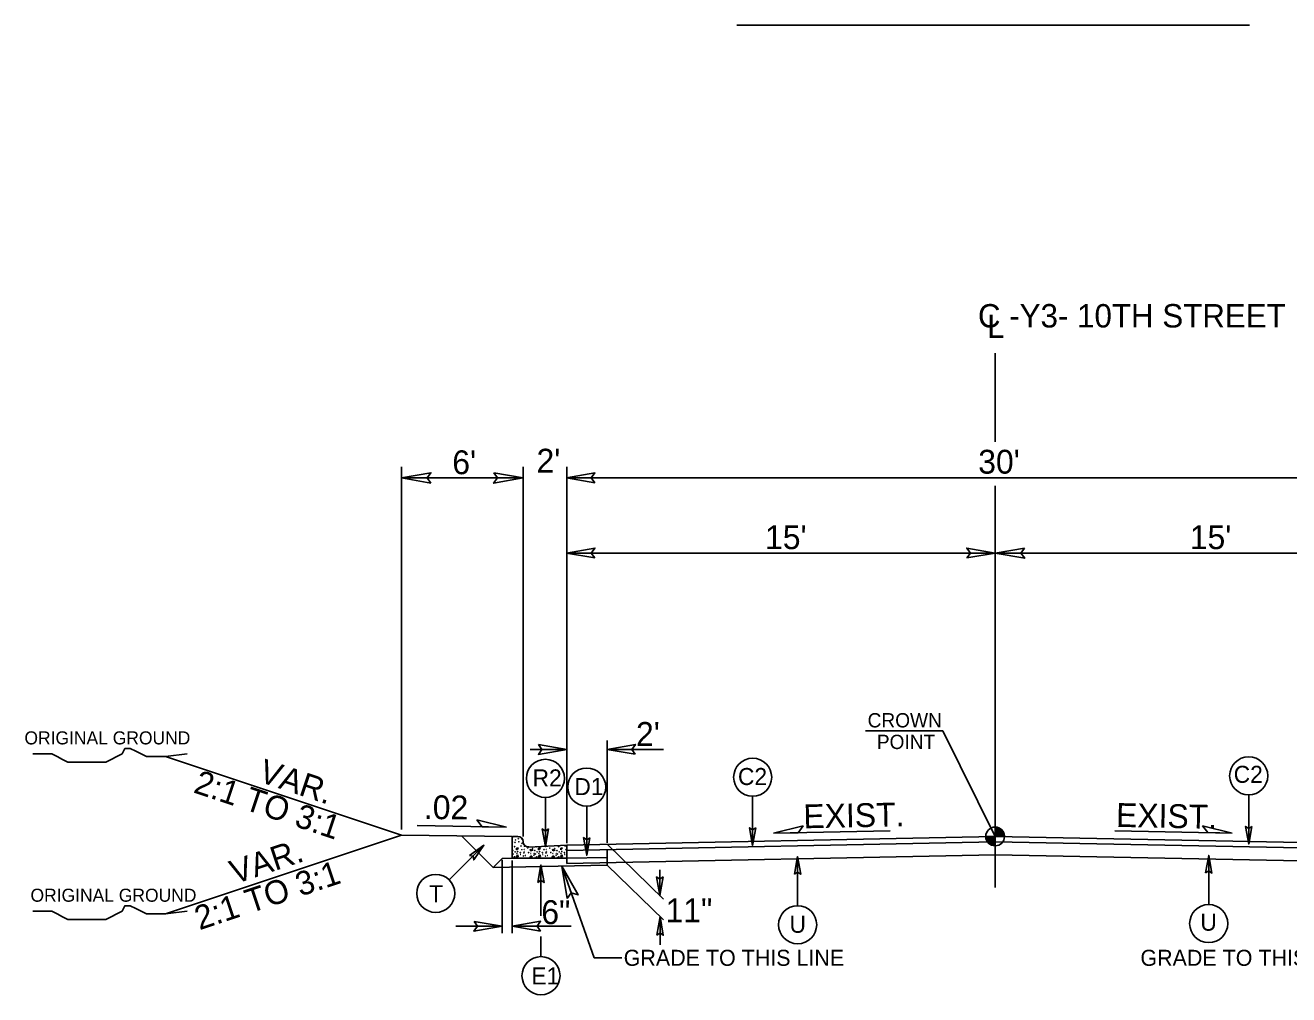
# Model space of a CAD drawing. Extents: x 957297 to 961629, y 830661 to 840840.
# Drawn here: x 959120.4 to 959533.8, y 835054.8 to 835371.9 of the extents above; entities that cross this region are included whole.
import ezdxf

# ---------------------------------------------------------------- set-up
doc = ezdxf.new("R2010")
doc.units = 0
for name, color, linetype in [('Default', 7, 'Continuous'), ('Old_Level_1', 7, 'Continuous'), ('Old_Level_11', 7, 'Continuous'), ('Old_Level_21', 7, 'Continuous'), ('Old_Level_3', 7, 'Continuous'), ('Prop Dimension Text', 7, 'Continuous'), ('Typical ID Circle CELL', 7, 'Continuous'), ('Typical Terminator CELL', 7, 'Continuous'), ('Typical Text Grade Point CELL', 7, 'Continuous'), ('Typical Text ID Circle CELL', 7, 'Continuous')]:
    doc.layers.add(name, color=color, linetype=linetype)

msp = doc.modelspace()

# ---------------------------------------------------------------- linework, layer by layer
at = {"layer": 'Default'}
for p, q in [((959437.72, 835264.61), (959437.72, 835235.64)), ((959437.72, 835221.25), (959437.72, 835089.87))]:
    msp.add_line(p, q, dxfattribs=at)
at = {"layer": 'Old_Level_1'}
for p, q in [((959520.94, 835371.89), (959353.24, 835371.89)), ((959243.49, 835108.77), (959243.49, 835227.43)), ((959283.31, 835106.54), (959283.31, 835227.43)), ((959297.55, 835104.3), (959297.55, 835227.43)), ((959243.49, 835223.8), (959283.31, 835223.8)), ((959297.55, 835223.8), (959577.94, 835223.8)), ((959297.5, 835199.24), (959437.72, 835199.24)), ((959437.72, 835199.24), (959577.94, 835199.24)), ((959285.62, 835135), (959297.55, 835135)), ((959310.76, 835104.5), (959310.76, 835137.93)), ((959310.76, 835135), (959329.24, 835135)), ((959243.49, 835106.92), (959166.3, 835132.65)), ((959248.67, 835110.14), (959277.89, 835109.56)), ((959437.72, 835106.53), (959437.72, 835109.6)), ((959166.3, 835081.19), (959243.49, 835106.92)), ((959243.49, 835106.92), (959279.75, 835106.56)), ((959273.48, 835096.4), (959263.16, 835106.72)), ((959437.72, 835106.54), (959297.55, 835103.71)), ((959403.38, 835108.39), (959365.21, 835107.62)), ((959434.66, 835106.53), (959437.72, 835106.53)), ((959437.72, 835106.54), (959577.94, 835103.71)), ((959440.78, 835106.53), (959437.72, 835106.53)), ((959437.72, 835103.49), (959437.72, 835106.53)), ((959437.72, 835106.53), (959437.72, 835103.49)), ((959476.83, 835108.43), (959515.29, 835107.66)), ((959437.72, 835104.82), (959297.55, 835101.98)), ((959437.72, 835104.82), (959297.55, 835101.98)), ((959297.55, 835101.98), (959297.55, 835097.71)), ((959310.76, 835103.98), (959329.23, 835086.05)), ((959310.76, 835102.25), (959310.76, 835097.15)), ((959437.72, 835104.82), (959577.94, 835101.98)), ((959437.72, 835104.82), (959577.94, 835101.98)), ((959276.45, 835099.37), (959273.48, 835096.4)), ((959310.76, 835097.15), (959273.48, 835096.4)), ((959279.75, 835099.43), (959276.45, 835099.37)), ((959276.45, 835074.88), (959276.45, 835098.92)), ((959279.75, 835074.88), (959279.75, 835098.63)), ((959437.72, 835100.54), (959297.55, 835097.71)), ((959310.76, 835099.7), (959297.55, 835099.43)), ((959310.76, 835097.15), (959329.23, 835079.22)), ((959437.72, 835100.54), (959577.94, 835097.71)), ((959306.5, 835066.86), (959295.97, 835096.85)), ((959328.02, 835095.58), (959328.02, 835087.22)), ((959261.26, 835077.17), (959276.45, 835077.17)), ((959279.75, 835077.17), (959299.02, 835077.17)), ((959328.08, 835080.33), (959328.09, 835071.11)), ((959315.54, 835066.86), (959306.5, 835066.86))]:
    msp.add_line(p, q, dxfattribs=at)
for points in [[(959437.76, 835109.6), (959437.76, 835109.6), (959437.76, 835106.53)], [(959437.81, 835109.6), (959437.81, 835106.53)], [(959437.87, 835109.59), (959437.87, 835106.53)], [(959437.94, 835109.59), (959437.94, 835106.53)], [(959438, 835109.59), (959438, 835106.53)], [(959438.06, 835109.59), (959438.06, 835106.53)], [(959438.12, 835109.57), (959438.12, 835106.53)], [(959438.18, 835109.57), (959438.18, 835106.53)], [(959438.23, 835109.55), (959438.23, 835106.53)], [(959438.3, 835109.55), (959438.3, 835106.53)], [(959434.68, 835106.53), (959434.68, 835106.21)], [(959434.74, 835106.53), (959434.74, 835105.85)], [(959434.8, 835106.53), (959434.8, 835105.63)], [(959434.86, 835106.53), (959434.86, 835105.45)], [(959434.93, 835106.53), (959434.93, 835105.3)], [(959434.99, 835106.53), (959434.99, 835105.17)], [(959435.05, 835106.53), (959435.05, 835105.06)], [(959435.11, 835106.53), (959435.11, 835104.95)], [(959435.17, 835106.53), (959435.17, 835104.86)], [(959435.23, 835106.53), (959435.23, 835104.77)], [(959435.3, 835106.53), (959435.3, 835104.68)], [(959435.36, 835106.53), (959435.36, 835104.61)], [(959435.42, 835106.53), (959435.42, 835104.54)], [(959435.47, 835106.53), (959435.47, 835104.47)], [(959435.53, 835106.53), (959435.53, 835104.4)], [(959435.6, 835106.53), (959435.6, 835104.35)], [(959435.66, 835106.53), (959435.66, 835104.29)], [(959435.72, 835106.53), (959435.72, 835104.23)], [(959435.78, 835106.53), (959435.78, 835104.19)], [(959435.85, 835106.53), (959435.85, 835104.12)], [(959435.9, 835106.53), (959435.9, 835104.09)], [(959435.96, 835106.53), (959435.96, 835104.04)], [(959436.02, 835106.53), (959436.02, 835104)], [(959436.09, 835106.53), (959436.09, 835103.95)], [(959436.15, 835106.53), (959436.15, 835103.91)], [(959436.21, 835106.53), (959436.21, 835103.87)], [(959436.28, 835106.53), (959436.28, 835103.84)], [(959436.33, 835106.53), (959436.33, 835103.83)], [(959436.39, 835106.53), (959436.39, 835103.79)], [(959436.46, 835106.53), (959436.46, 835103.75)], [(959436.52, 835106.53), (959436.52, 835103.74)], [(959436.58, 835106.53), (959436.58, 835103.7)], [(959436.64, 835106.53), (959436.64, 835103.68)], [(959436.7, 835106.53), (959436.7, 835103.66)], [(959436.75, 835106.53), (959436.75, 835103.64)], [(959436.82, 835106.53), (959436.82, 835103.62)], [(959436.88, 835106.53), (959436.88, 835103.6)], [(959436.94, 835106.53), (959436.94, 835103.59)], [(959437, 835106.53), (959437, 835103.58)], [(959437.07, 835106.53), (959437.07, 835103.56)], [(959437.13, 835106.53), (959437.13, 835103.54)], [(959437.19, 835106.53), (959437.19, 835103.54)], [(959437.25, 835106.53), (959437.25, 835103.52)], [(959437.31, 835106.53), (959437.31, 835103.5)], [(959437.38, 835106.53), (959437.38, 835103.5)], [(959437.44, 835106.53), (959437.44, 835103.5)], [(959437.5, 835106.53), (959437.5, 835103.49)], [(959437.56, 835106.53), (959437.56, 835103.49)], [(959437.61, 835106.53), (959437.61, 835103.49)], [(959437.67, 835106.53), (959437.67, 835103.49), (959437.67, 835103.49)], [(959438.36, 835109.53), (959438.36, 835106.53)], [(959438.42, 835109.52), (959438.42, 835106.53)], [(959438.49, 835109.49), (959438.49, 835106.53)], [(959438.55, 835109.48), (959438.55, 835106.53)], [(959438.61, 835109.46), (959438.61, 835106.53)], [(959438.67, 835109.44), (959438.67, 835106.53)], [(959438.74, 835109.43), (959438.73, 835106.53)], [(959438.79, 835109.4), (959438.79, 835106.53)], [(959438.85, 835109.39), (959438.85, 835106.53)], [(959438.92, 835109.36), (959438.92, 835106.53)], [(959438.98, 835109.34), (959438.98, 835106.53)], [(959439.04, 835109.3), (959439.04, 835106.53)], [(959439.09, 835109.27), (959439.09, 835106.53)], [(959439.15, 835109.25), (959439.15, 835106.53)], [(959439.21, 835109.21), (959439.21, 835106.53)], [(959439.28, 835109.18), (959439.28, 835106.53)], [(959439.34, 835109.14), (959439.34, 835106.53)], [(959439.4, 835109.09), (959439.4, 835106.53)], [(959439.47, 835109.05), (959439.47, 835106.53)], [(959439.52, 835109.02), (959439.52, 835106.53)], [(959439.59, 835108.96), (959439.59, 835106.53)], [(959439.65, 835108.92), (959439.65, 835106.53)], [(959439.71, 835108.87), (959439.71, 835106.53)], [(959439.77, 835108.81), (959439.77, 835106.53)], [(959439.83, 835108.75), (959439.83, 835106.53)], [(959439.9, 835108.69), (959439.9, 835106.53)], [(959439.95, 835108.63), (959439.95, 835106.53)], [(959440.01, 835108.57), (959440.01, 835106.53)], [(959440.07, 835108.5), (959440.07, 835106.53)], [(959440.13, 835108.41), (959440.13, 835106.53)], [(959440.2, 835108.33), (959440.2, 835106.53)], [(959440.26, 835108.25), (959440.26, 835106.53)], [(959440.32, 835108.16), (959440.32, 835106.53)], [(959440.38, 835108.05), (959440.38, 835106.53)], [(959440.44, 835107.95), (959440.44, 835106.53)], [(959440.5, 835107.8), (959440.5, 835106.53)], [(959440.57, 835107.66), (959440.57, 835106.53)], [(959440.63, 835107.5), (959440.63, 835106.53)], [(959440.69, 835107.28), (959440.69, 835106.53)], [(959440.75, 835106.98), (959440.75, 835106.53)]]:
    msp.add_lwpolyline(points, dxfattribs=at)
msp.add_circle((959437.72, 835106.54), 3.06, dxfattribs=at)
for start, end in [(359.9905, 89.9905), (179.9905, 269.9905)]:
    msp.add_arc((959437.72, 835106.54), 3.06, start, end, dxfattribs=at)
at = {"layer": 'Old_Level_11'}
for p, q in [((959269.88, 835109.71), (959268.15, 835111.97)), ((959268.15, 835111.97), (959277.89, 835109.56)), ((959277.89, 835109.56), (959269.88, 835109.71)), ((959365.21, 835107.62), (959374.96, 835110.04)), ((959374.96, 835110.04), (959373.23, 835107.78)), ((959507.28, 835107.82), (959505.55, 835110.07)), ((959505.55, 835110.07), (959515.29, 835107.66)), ((959373.23, 835107.78), (959365.21, 835107.62)), ((959515.29, 835107.66), (959507.28, 835107.82))]:
    msp.add_line(p, q, dxfattribs=at)
for points in [[(959253.1, 835222.14), (959243.49, 835223.8), (959253.15, 835225.51), (959251.93, 835223.8)], [(959273.71, 835225.45), (959283.31, 835223.8), (959273.65, 835222.08), (959274.88, 835223.8)], [(959447.33, 835200.89), (959437.72, 835199.24), (959447.39, 835197.52), (959446.16, 835199.24)], [(959297.74, 835086.27), (959295.97, 835096.85), (959301.25, 835087.43), (959299.04, 835088.1)]]:
    msp.add_lwpolyline(points, close=True, dxfattribs=at)
at = {"layer": 'Old_Level_21'}
for points in [[(959173.4, 835133.53), (959166.3, 835132.65), (959164.53, 835132.65), (959161.87, 835132.65), (959160.09, 835132.65), (959158.32, 835133.53), (959156.54, 835134.43), (959154.77, 835135.31), (959153, 835135.31), (959152.1, 835133.53), (959150.34, 835132.65), (959148.56, 835131.76), (959146.79, 835130.88), (959145.02, 835130.88), (959143.25, 835130.88), (959141.47, 835130.88), (959139.7, 835130.88), (959137.92, 835130.88), (959136.15, 835130.88), (959134.38, 835130.88), (959132.61, 835131.76), (959130.84, 835132.65), (959129.07, 835133.53), (959126.39, 835133.53), (959124.62, 835133.53), (959122.85, 835133.53)], [(959173.4, 835082.07), (959166.3, 835081.19), (959164.53, 835081.19), (959161.87, 835081.19), (959160.09, 835081.19), (959158.32, 835082.07), (959156.54, 835082.97), (959154.77, 835083.85), (959153, 835083.85), (959152.1, 835082.07), (959150.34, 835081.19), (959148.56, 835080.29), (959146.79, 835079.42), (959145.02, 835079.42), (959143.25, 835079.42), (959141.47, 835079.42), (959139.7, 835079.42), (959137.92, 835079.42), (959136.15, 835079.42), (959134.38, 835079.42), (959132.61, 835080.29), (959130.84, 835081.19), (959129.07, 835082.07), (959126.39, 835082.07), (959124.62, 835082.07), (959122.85, 835082.07)]]:
    msp.add_lwpolyline(points, dxfattribs=at)
at = {"layer": 'Old_Level_3'}
for p, q in [((959279.75, 835103), (959279.75, 835106.25)), ((959280.06, 835106.56), (959281.54, 835106.56)), ((959279.75, 835099.43), (959279.75, 835103)), ((959281.12, 835102.74), (959281.12, 835102.12)), ((959281.75, 835102.71), (959281.12, 835102.74)), ((959281.12, 835102.12), (959281.75, 835102.71)), ((959283.46, 835104.36), (959283.34, 835104.2)), ((959283.34, 835104.2), (959283.5, 835104.24)), ((959285.16, 835103.09), (959297.55, 835103.71)), ((959285.16, 835103.09), (959285.16, 835103.09)), ((959285.65, 835102.31), (959285.75, 835101.79)), ((959286.54, 835102.06), (959285.65, 835102.31)), ((959285.75, 835101.79), (959286.54, 835102.06)), ((959288.35, 835102.74), (959288.35, 835102.12)), ((959288.98, 835102.71), (959288.35, 835102.74)), ((959288.35, 835102.12), (959288.98, 835102.71)), ((959292.88, 835102.31), (959292.98, 835101.79)), ((959293.77, 835102.06), (959292.88, 835102.31)), ((959292.98, 835101.79), (959293.77, 835102.06)), ((959295.58, 835102.74), (959295.58, 835102.12)), ((959296.2, 835102.71), (959295.58, 835102.74)), ((959295.58, 835102.12), (959296.2, 835102.71)), ((959297.55, 835103.71), (959297.55, 835099.43)), ((959297.55, 835099.43), (959279.75, 835099.43)), ((959281.03, 835099.84), (959281.53, 835100.54)), ((959281.71, 835099.88), (959281.03, 835099.84)), ((959281.53, 835100.54), (959281.71, 835099.88)), ((959285.45, 835099.55), (959285.81, 835100.21)), ((959286.41, 835099.78), (959285.45, 835099.55)), ((959285.81, 835100.21), (959286.41, 835099.78)), ((959288.26, 835099.84), (959288.75, 835100.54)), ((959288.94, 835099.88), (959288.26, 835099.84)), ((959288.75, 835100.54), (959288.94, 835099.88)), ((959292.68, 835099.55), (959293.04, 835100.21)), ((959293.64, 835099.78), (959292.68, 835099.55)), ((959293.04, 835100.21), (959293.64, 835099.78)), ((959295.48, 835099.84), (959295.98, 835100.54)), ((959296.17, 835099.88), (959295.48, 835099.84)), ((959295.98, 835100.54), (959296.17, 835099.88))]:
    msp.add_line(p, q, dxfattribs=at)
for centre in [(959280.8, 835105.39), (959281.72, 835105.79), (959282.91, 835105.66), (959279.81, 835104.7), (959279.91, 835101.92), (959280.5, 835103.21), (959280.63, 835104.6), (959280.66, 835101.49), (959281.49, 835101.59), (959281.89, 835104.8), (959282.35, 835101.23), (959282.58, 835103.41), (959282.88, 835102.22), (959282.94, 835104.27), (959283.64, 835101.43), (959283.67, 835102.28), (959283.77, 835103.38), (959284.83, 835102.71), (959285.12, 835101.26), (959286.38, 835102.55), (959287.14, 835101.92), (959287.89, 835101.49), (959288.72, 835101.59), (959289.58, 835101.23), (959290.11, 835102.22), (959290.86, 835101.43), (959290.9, 835102.28), (959292.05, 835102.71), (959292.35, 835101.26), (959293.61, 835102.55), (959294.37, 835101.92), (959294.95, 835103.21), (959295.12, 835101.49), (959295.94, 835101.59), (959296.8, 835101.23), (959297.03, 835103.41), (959297.33, 835102.22), (959279.95, 835099.58), (959280.04, 835100.77), (959280.5, 835099.85), (959281.23, 835101), (959282.51, 835100.64), (959283.37, 835100.14), (959283.54, 835101.14), (959284.1, 835100.31), (959285.82, 835100.97), (959286.84, 835100.41), (959286.94, 835100.97), (959287.17, 835099.58), (959287.26, 835100.77), (959287.73, 835099.85), (959288.45, 835101), (959289.74, 835100.64), (959290.6, 835100.14), (959290.77, 835101.14), (959291.33, 835100.31), (959293.05, 835100.97), (959294.07, 835100.41), (959294.17, 835100.97), (959294.4, 835099.58), (959294.49, 835100.77), (959294.95, 835099.85), (959295.68, 835101), (959296.97, 835100.64)]:
    msp.add_circle(centre, 0.0464, dxfattribs=at)
for centre, radius, start, end in [((959280.06, 835106.25), 0.309, 90, 180), ((959279.95, 835106.48), 0.0464, 259.6531, 10.3469), ((959281.54, 835104.78), 1.78, 1.0734, 90), ((959285.07, 835104.85), 1.76, 181.0734, 272.8624), ((959287.73, 835103.21), 0.0464, 167.7795, 17.938), ((959291, 835103.38), 0.0464, 169.8374, 15.8801), ((959279.71, 835100.97), 0.0464, 330.4173, 29.5827)]:
    msp.add_arc(centre, radius, start, end, dxfattribs=at)
at = {"layer": 'Typical ID Circle CELL'}
for p, q in [((959290.59, 835119.32), (959290.59, 835103.23)), ((959358.39, 835119.69), (959358.39, 835103.6)), ((959520.68, 835120.14), (959520.68, 835104.06)), ((959304.1, 835116.46), (959304.1, 835100.38)), ((959259.12, 835092.31), (959270.49, 835103.68)), ((959289.14, 835080.55), (959289.14, 835097.25)), ((959373.11, 835083.87), (959373.11, 835099.96)), ((959507.59, 835084.27), (959507.59, 835100.36)), ((959289.14, 835067.22), (959289.14, 835073.85))]:
    msp.add_line(p, q, dxfattribs=at)
for centre in [(959290.59, 835125.54), (959358.39, 835125.91), (959520.68, 835126.37), (959304.1, 835122.69), (959254.72, 835087.91), (959373.11, 835077.65), (959507.59, 835078.05), (959289.14, 835060.99)]:
    msp.add_circle(centre, 6.23, dxfattribs=at)
at = {"layer": 'Typical Terminator CELL'}
for points in [[(959306.72, 835222.21), (959297.5, 835223.8), (959306.77, 835225.44), (959305.59, 835223.8)], [(959306.72, 835197.65), (959297.5, 835199.24), (959306.77, 835200.88), (959305.59, 835199.24)], [(959428.5, 835197.65), (959437.72, 835199.24), (959428.44, 835200.88), (959429.62, 835199.24)], [(959288.33, 835136.59), (959297.55, 835135), (959288.28, 835133.36), (959289.46, 835135)], [(959319.98, 835133.41), (959310.76, 835135), (959320.03, 835136.64), (959318.85, 835135)], [(959521.67, 835109.82), (959520.68, 835104.06), (959519.66, 835109.85), (959520.68, 835109.12)], [(959291.58, 835108.99), (959290.59, 835103.23), (959289.56, 835109.02), (959290.59, 835108.29)], [(959305.09, 835106.14), (959304.1, 835100.38), (959303.08, 835106.17), (959304.1, 835105.44)], [(959359.39, 835109.36), (959358.39, 835103.6), (959357.37, 835109.39), (959358.39, 835108.66)], [(959265.72, 835100.31), (959270.49, 835103.68), (959267.12, 835098.86), (959266.92, 835100.11)], [(959288.15, 835091.49), (959289.14, 835097.25), (959290.17, 835091.45), (959289.14, 835092.19)], [(959372.12, 835094.2), (959373.11, 835099.96), (959374.13, 835094.16), (959373.11, 835094.9)], [(959506.6, 835094.6), (959507.59, 835100.36), (959508.62, 835094.57), (959507.59, 835095.3)], [(959329.07, 835093.29), (959328.02, 835087.22), (959326.94, 835093.32), (959328.02, 835092.55)], [(959267.23, 835078.76), (959276.45, 835077.17), (959267.18, 835075.53), (959268.36, 835077.17)], [(959288.97, 835075.58), (959279.75, 835077.17), (959289.03, 835078.81), (959287.85, 835077.17)], [(959327.04, 835074.26), (959328.08, 835080.33), (959329.16, 835074.23), (959328.09, 835075)]]:
    msp.add_lwpolyline(points, close=True, dxfattribs=at)
at = {"layer": 'Typical Text Grade Point CELL'}
for p, q in [((959395.28, 835141.1), (959420.61, 835141.1)), ((959420.61, 835141.1), (959437.72, 835106.53))]:
    msp.add_line(p, q, dxfattribs=at)

# ---------------------------------------------------------------- texts
at = {"layer": 'Old_Level_1'}
for s, height, p in [("30'", 7.801, (959432.19, 835225.22)), ("15'", 7.801, (959362.45, 835200.53)), ("15'", 7.801, (959501.41, 835200.53)), ('GRADE TO THIS LINE', 5.2473, (959316.2, 835064.22)), ('GRADE TO THIS LINE', 5.2473, (959485.25, 835064.22))]:
    msp.add_text(s, height=height, dxfattribs=at).set_placement(p)
at = {"layer": 'Old_Level_11'}
for s, height, p in [('CROWN', 4.671, (959396, 835142.21)), ('POINT', 4.671, (959399.02, 835135.14)), ('11"', 7.801, (959329.9, 835078.46))]:
    msp.add_text(s, height=height, dxfattribs=at).set_placement(p)
at = {"layer": 'Old_Level_21'}
for p in [(959120.14, 835136.65), (959122.13, 835085.18)]:
    msp.add_text('ORIGINAL GROUND', height=4.2722, dxfattribs=at).set_placement(p)
at = {"layer": 'Old_Level_3'}
for s, height, p in [('C -Y3- 10TH STREET', 7.6574, (959432.1, 835273.03)), ('L', 7.66, (959435.09, 835269.57)), ("6'", 7.801, (959260.12, 835225.04)), ("2'", 7.801, (959287.68, 835225.56))]:
    msp.add_text(s, height=height, dxfattribs=at).set_placement(p)
for s, rotation, p in [('VAR.', 341.5652, (959196.34, 835124.62)), ('2:1 TO 3:1', 341.5652, (959175.09, 835121.04)), ('.02', 359.4336, (959250.8, 835112.24)), ('VAR.', 18.4348, (959188.97, 835090.86)), ('2:1 TO 3:1', 18.4348, (959177.41, 835075.84))]:
    msp.add_text(s, height=7.801, rotation=rotation, dxfattribs=at).set_placement(p)
at = {"layer": 'Prop Dimension Text'}
for s, rotation, p in [("2'", 0, (959320.23, 835136.16)), ('EXIST.', 1.1839, (959375.07, 835109.2)), ('EXIST.', 358.8533, (959477.22, 835109.68)), ('6"', 0, (959289.25, 835077.88))]:
    msp.add_text(s, height=7.801, rotation=rotation, dxfattribs=at).set_placement(p)
at = {"layer": 'Typical Text ID Circle CELL'}
for s, height, p in [('R2', 5.572, (959286.39, 835122.91)), ('C2', 5.572, (959353.58, 835123.36)), ('C2', 5.572, (959515.77, 835124.08)), ('D1', 5.572, (959300.05, 835120.06)), ('U', 5.57, (959370.46, 835075.03)), ('E1', 5.572, (959286, 835058.14))]:
    msp.add_text(s, height=height, dxfattribs=at).set_placement(p)
for s, p in [('T', (959252.54, 835085.03)), ('U', (959504.85, 835075.71))]:
    msp.add_text(s, height=5.57, rotation=360, dxfattribs=at).set_placement(p)

doc.saveas('drawing.dxf')
